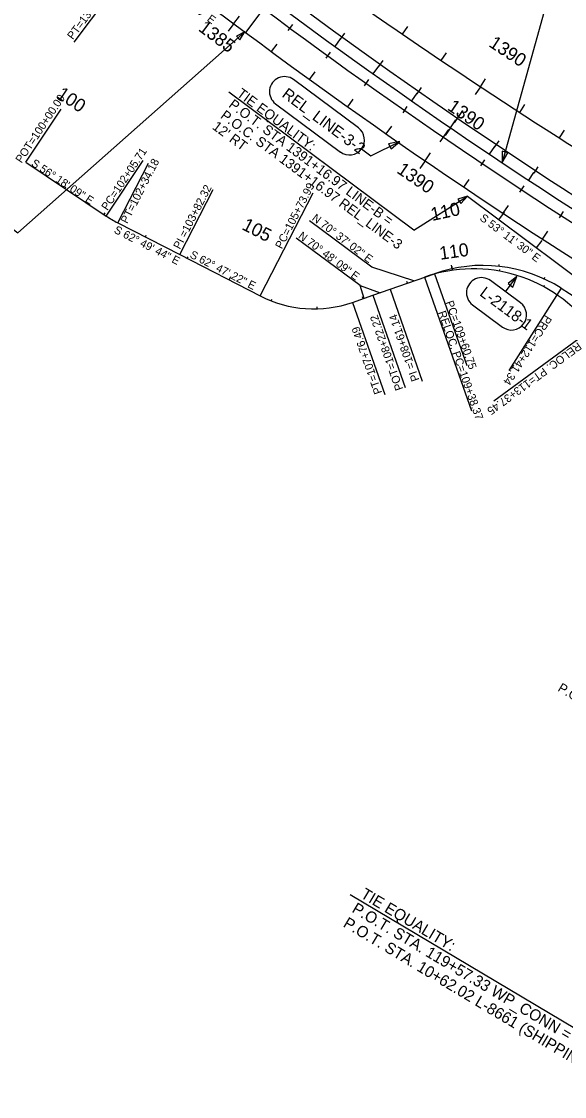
# Model space of a CAD drawing. Extents: x 2339300 to 2355400, y 360879 to 381052.
# Drawn here: x 2344770 to 2345923, y 368212 to 370495 of the extents above; entities that cross this region are included whole.
import ezdxf

# ---------------------------------------------------------------- set-up
doc = ezdxf.new("R2010")
doc.units = 0
for name, color, linetype in [('RD_HC_Cl', 7, 'Continuous'), ('RD_HC_CL_Rel', 7, 'Continuous'), ('RD_HC_Data', 7, 'Continuous'), ('RD_HC_Data_Rel', 7, 'Continuous'), ('RD_HC_Data_Tic', 7, 'Continuous'), ('RD_HC_Data_Tic_Rel', 7, 'Continuous'), ('RD_HC_TX_Rel_Sta50', 7, 'Continuous'), ('RD_HC_TX_Sta50', 7, 'Continuous'), ('RD_PD_Final_TX', 7, 'Continuous')]:
    doc.layers.add(name, color=color, linetype=linetype)

msp = doc.modelspace()

# ---------------------------------------------------------------- linework, layer by layer
at = {"layer": 'RD_HC_Cl'}
for p, q in [((2344778.6, 370196.2), (2344949.7, 370082)), ((2345717.1, 370123.9), (2346548.7, 369501.6)), ((2344974.3, 370067.6), (2345106, 370000)), ((2345106, 370000), (2345276.5, 369912.3)), ((2345553, 369926.4), (2345646.9, 369959.5)), ((2345516.2, 369913.6), (2345553, 369926.4)), ((2345473, 369898.6), (2345516.2, 369913.6))]:
    msp.add_line(p, q, dxfattribs=at)
for centre, radius, start, end in [((2352034, 379865.6), 11400.7, 232.99132, 241.72492), ((2352152.8, 379726.2), 11459.2, 233.26372, 239.17851), ((2345088.4, 370290), 250, 236.3026, 242.8289), ((2345749.8, 369667), 310, 57.5217, 109.3829), ((2352152.8, 379726.2), 11614.2, 237.52174, 239.17851), ((2345390.8, 370134.7), 250, 242.7895, 289.1976)]:
    msp.add_arc(centre, radius, start, end, dxfattribs=at)
at = {"layer": 'RD_HC_CL_Rel'}
msp.add_line((2345022, 370639), (2345245.9, 370472), dxfattribs=at)
for centre, radius, start, end in [((2352152.8, 379726.2), 11434, 233.26372, 239.17851), ((2352152.8, 379726.2), 11484.3, 233.26372, 239.17851), ((2352152.8, 379726.2), 11547.6, 233.26372, 239.17851), ((2345729.7, 369656.8), 313, 36.3291, 109.3829)]:
    msp.add_arc(centre, radius, start, end, dxfattribs=at)
at = {"layer": 'RD_HC_Data'}
for p, q in [((2345485.3, 370269.3), (2345347.5, 370371.9)), ((2344778.6, 370196.2), (2344853.7, 370308.8)), ((2345309.3, 370320.6), (2345447.1, 370218)), ((2344949.7, 370082), (2345028.5, 370200.2)), ((2344974.3, 370067.6), (2345039.4, 370194.6)), ((2345106, 370000), (2345177, 370138.2)), ((2345276.5, 369912.3), (2345389.2, 370131.5)), ((2345646.9, 369959.5), (2345715.6, 369764.2)), ((2345829.6, 369897.5), (2345766, 369944.8)), ((2345489, 369934.2), (2345531.9, 369918.9)), ((2345553, 369926.4), (2345620.8, 369731.5)), ((2345916.3, 369928.5), (2345804.8, 369753.5)), ((2345473, 369898.6), (2345541.2, 369702.8)), ((2345516.2, 369913.6), (2345584.4, 369717.8)), ((2345727.8, 369893.4), (2345791.4, 369846.1)), ((2345990, 368328.8), (2345468, 368640.3))]:
    msp.add_line(p, q, dxfattribs=at)
for points in [[(2345901.5, 370738), (2345934.3, 370713.6), (2345790.6, 370195.5)], [(2345491.9, 370224.6), (2345512, 370209.6), (2345573.1, 370240.5)], [(2345603.1, 369944), (2345514.1, 369973), (2345381.2, 370071.9)], [(2345497.5, 369907.1), (2345489, 369934.2), (2345353.2, 370035.2)], [(2345798, 369921), (2345822.1, 369953.4)]]:
    msp.add_lwpolyline(points, dxfattribs=at)
for points in [[(2345555.2, 370224.5), (2345573.1, 370240.5), (2345549.6, 370235.6)], [(2345790.8, 370219.5), (2345790.6, 370195.5), (2345802.7, 370216.2)], [(2345813.3, 369931.1), (2345822.1, 369953.4), (2345803.3, 369938.5)]]:
    msp.add_lwpolyline(points, close=True, dxfattribs=at)
for centre, start, end in [((2345328.4, 370346.2), 53.3467, 233.3467), ((2345466.2, 370243.7), 233.3467, 53.3467), ((2345746.9, 369919.1), 53.3467, 233.3467), ((2345810.5, 369871.8), 233.3467, 53.3467)]:
    msp.add_arc(centre, 32, start, end, dxfattribs=at)
at = {"layer": 'RD_HC_Data_Rel'}
for p, q in [((2344881.9, 370451.2), (2345022, 370639)), ((2345625.8, 369952), (2345725.8, 369667.8)), ((2345981.9, 369842.2), (2345773.3, 369688.8))]:
    msp.add_line(p, q, dxfattribs=at)
at = {"layer": 'RD_HC_Data_Tic'}
for p, q in [((2345578.8, 370468.5), (2345590.1, 370484.9)), ((2345435.7, 370442.2), (2345447.4, 370458.4)), ((2345661.5, 370412.2), (2345672.7, 370428.8)), ((2345517, 370383.9), (2345528.6, 370400.2)), ((2345744.7, 370356.7), (2345755.7, 370373.3)), ((2345744.7, 370356.7), (2345733.6, 370340)), ((2345598.8, 370326.4), (2345610.2, 370342.8)), ((2345828.3, 370301.9), (2345839.2, 370318.6)), ((2345681, 370269.5), (2345692.3, 370286)), ((2345681, 370269.5), (2345669.8, 370253)), ((2345912.4, 370247.8), (2345923.2, 370264.7)), ((2345763.8, 370213.4), (2345775, 370230)), ((2344778.6, 370196.2), (2344783, 370202.8)), ((2345847.1, 370158), (2345858.1, 370174.7)), ((2344861.8, 370140.7), (2344864, 370144)), ((2344945, 370085.2), (2344947.2, 370088.5)), ((2345783.6, 370074.1), (2345795.5, 370090.1)), ((2345032.8, 370037.6), (2345034.6, 370041.1)), ((2345863.6, 370014.2), (2345875.6, 370030.2)), ((2345121.8, 369991.9), (2345123.6, 369995.4)), ((2345684.7, 369970.1), (2345683, 369977.9)), ((2345784.1, 369975.1), (2345784.6, 369979.1)), ((2345210.7, 369946.2), (2345214.4, 369953.3)), ((2345589.6, 369939.3), (2345588.3, 369943.1)), ((2345880, 369948.3), (2345881.7, 369952)), ((2345300.2, 369901.7), (2345301.7, 369905.4)), ((2345495.2, 369906.3), (2345493.9, 369910.1)), ((2345398.1, 369884.8), (2345398, 369888.8))]:
    msp.add_line(p, q, dxfattribs=at)
at = {"layer": 'RD_HC_Data_Tic_Rel'}
for p, q in [((2345220.6, 370490.8), (2345208.7, 370474.8)), ((2345220.6, 370490.8), (2345232.6, 370506.8)), ((2345336.3, 370476.2), (2345345.8, 370489.1)), ((2345447.2, 370457.6), (2345456.6, 370470.5)), ((2345300.9, 370431.2), (2345312.8, 370447.3)), ((2345417.1, 370417.2), (2345426.4, 370430.2)), ((2345528.5, 370399.3), (2345537.8, 370412.3)), ((2345381.7, 370372.2), (2345393.4, 370388.4)), ((2345498.4, 370358.9), (2345507.6, 370372)), ((2345610.3, 370341.7), (2345619.5, 370354.8)), ((2345462.9, 370313.9), (2345474.5, 370330.2)), ((2345580.2, 370301.3), (2345589.3, 370314.5)), ((2345689.3, 370279.9), (2345707.3, 370306.3)), ((2345544.7, 370256.3), (2345556.1, 370272.7)), ((2345659.1, 370239.5), (2345677.2, 370265.9)), ((2345775.5, 370228.7), (2345784.4, 370242)), ((2345626.9, 370199.4), (2345638.2, 370215.9)), ((2345626.9, 370199.4), (2345615.6, 370182.9)), ((2345745.3, 370188.3), (2345754.2, 370201.6)), ((2345858.8, 370173.3), (2345867.6, 370186.6)), ((2345709.7, 370143.3), (2345720.8, 370159.9)), ((2345828.6, 370132.9), (2345837.4, 370146.2)), ((2345792.9, 370087.8), (2345803.9, 370104.5)), ((2345912.4, 370078.2), (2345921.1, 370091.6)), ((2345876.6, 370033.1), (2345887.5, 370049.9)), ((2345685.6, 369966.6), (2345684.5, 369974.6)), ((2345785.1, 369964.8), (2345785.9, 369968.7)), ((2345879.1, 369931.8), (2345881, 369935.3))]:
    msp.add_line(p, q, dxfattribs=at)
at = {"layer": 'RD_PD_Final_TX'}
for p, q in [((2345313.8, 370563), (2345245.9, 370472)), ((2345603.1, 370052.3), (2345209.8, 370344.9))]:
    msp.add_line(p, q, dxfattribs=at)
for points in [[(2344721.9, 370075.7), (2344761.8, 370046), (2345244.4, 370473.1)], [(2345603.1, 370052.3), (2345717.1, 370123.9)]]:
    msp.add_lwpolyline(points, dxfattribs=at)
for points in [[(2345233.4, 370456.4), (2345244.4, 370473.1), (2345226.5, 370464.2)], [(2345702.7, 370108.4), (2345717.1, 370123.9), (2345696.9, 370117.6)]]:
    msp.add_lwpolyline(points, close=True, dxfattribs=at)

# ---------------------------------------------------------------- texts
at = {"layer": 'RD_HC_Data'}
for s, height, rotation, p in [('REL_LINE-3-2', 24, 323.3467, (2345321.2, 370336.6)), ('POT=100+00.00', 17, 56.3026, (2344769.7, 370193.2)), ('PC=102+05.71', 17, 56.3026, (2344952.1, 370092.5)), ('S 56%%d 18\' 09" E', 17, 326.3026, (2344788.8, 370190.2)), ('PT=102+34.18', 17, 62.8289, (2344994.3, 370064.6)), ('PI =103+82.32', 17, 62.8289, (2345106.2, 370010.1)), ('PC=105+73.99', 17, 62.7895, (2345322.7, 370010.8)), ('N 70%%d 37\' 02" E', 17, 322.6697, (2345385.3, 370074.6)), ('S 53%%d 11\' 30" E', 17, 323.1918, (2345741.8, 370074.6)), ('S 62%%d 49\' 44" E', 17, 332.8289, (2344964.6, 370047.3)), ('N 70%%d 48\' 09" E', 17, 323.2686, (2345356.1, 370036.5)), ('S 62%%d 47\' 22" E', 17, 332.7895, (2345125.9, 369994.5)), ('L-2118-1', 24, 323.3467, (2345741.2, 369914.5)), ('PC=109+60.75', 17, 289.3829, (2345670.4, 369898.8)), ('POT=108+22.22', 17, 109.1976, (2345580.9, 369714.8)), ('PI =108+61.14', 17, 109.1976, (2345615.1, 369734.1)), ('PRC=112+41.34', 17, 237.5217, (2345883.1, 369872.6)), ('PT=107+76.49', 17, 109.1976, (2345536, 369706.8)), ('TIE EQUALITY:', 24, 329.1784, (2345488.2, 368635.2)), ('P.O.T. STA. 119+57.33 WP_CONN =', 24, 329.1784, (2345469.8, 368604.3)), ('P.O.T. STA. 10+62.02 L-8661 (SHIPPING LANE)', 24, 329.1784, (2345451.3, 368573.4))]:
    msp.add_text(s, height=height, rotation=rotation, dxfattribs=at).set_placement(p)
at = {"layer": 'RD_HC_Data_Rel'}
for s, rotation, p in [('PT=1382+52.17', 53.2637, (2344878.9, 370455.4)), ('S 53%%d 15\' 49" E', 323.2637, (2345051.9, 370580.1)), ('RELOC. PC=109+38.37', 289.3829, (2345654.3, 369877.2)), ('RELOC. PT=113+37.45', 216.3291, (2345951.5, 369814.8))]:
    msp.add_text(s, height=17, rotation=rotation, dxfattribs=at).set_placement(p)
at = {"layer": 'RD_HC_TX_Rel_Sta50'}
for s, rotation, p in [('1385', 323.2637, (2345143.6, 370477.1)), ('1390', 325.5885, (2345565.1, 370175.1)), ('110', 8.1008, (2345659.4, 369988.8))]:
    msp.add_text(s, height=28, rotation=rotation, dxfattribs=at).set_placement(p)
at = {"layer": 'RD_HC_TX_Sta50'}
for s, rotation, p in [('1390', 326.5189, (2345760.6, 370443.4)), ('100', 326.3026, (2344842.1, 370335.1)), ('1390', 325.6136, (2345672.7, 370308.9)), ('110', 12.1281, (2345642.2, 370071.4)), ('105', 332.7895, (2345236, 370054.6))]:
    msp.add_text(s, height=28, rotation=rotation, dxfattribs=at).set_placement(p)
at = {"layer": 'RD_PD_Final_TX'}
for s, height, rotation, p in [('TIE EQUALITY:', 21.12, 323.3467, (2345225.4, 370338.2)), ('P.O.T. STA 1391+16.97 LINE-B =', 21.12, 323.3467, (2345208.1, 370314.9)), ('P.O.C. STA 1391+16.97 REL_LINE-3', 21.12, 323.3467, (2345190.7, 370291.6)), ("12' RT", 21.12, 323.3467, (2345173.4, 370268.3)), ('P.O.C STA. 121+84.44 REL L-2118', 20, 329.1784, (2345907.3, 369074.1))]:
    msp.add_text(s, height=height, rotation=rotation, dxfattribs=at).set_placement(p)

doc.saveas('drawing.dxf')
